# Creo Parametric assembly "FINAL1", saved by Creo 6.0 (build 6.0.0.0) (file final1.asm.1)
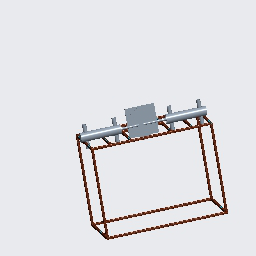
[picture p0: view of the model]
Units: millimeter Newton Second (mmNs); MM, TONNE, SECS

Created from: MMNS_ASM_DESIGN.ASM

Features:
  1. datum plane "ASM_RIGHT"
  2. datum plane "ASM_TOP"
  3. datum plane "ASM_FRONT"
  4. coordinate system
  5. component "ASM0001"
  6. component "CYLINDER"
  7. component "BAASE"
  8. component "CAM"
  9. component "CYLINDER"
  10. component "ASM0002"
  11. feature "Motor 1"
  12. component "CAP"
  13. component "CAP2"
  14. component "CAP"
  15. component "CAP2"

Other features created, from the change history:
  component "PRT0001.PRT"
  component "ASM0002.ASM" (2 times)
  feature "Motor 1" (2 times)
  feature "Motor 2" (2 times)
